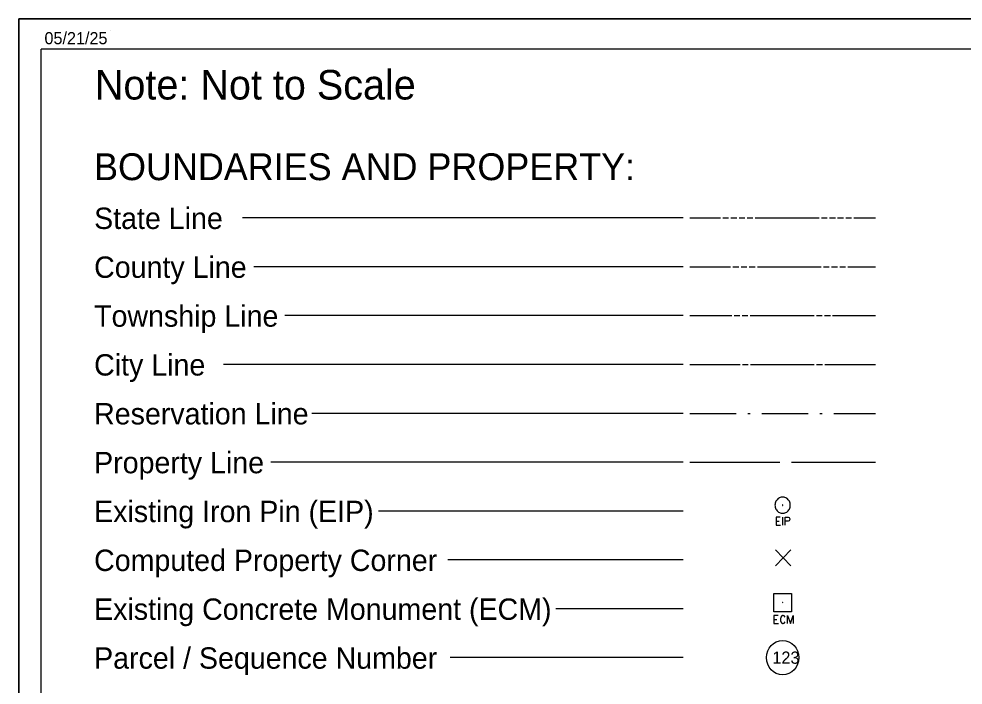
# Model space of a CAD drawing. Extents: x 2025847 to 2026166, y 840763 to 840870.
# Drawn here: x 2026023.88 to 2026057.38, y 840846.45 to 840870.09 of the extents above; entities that cross this region are included whole.
import ezdxf

# ---------------------------------------------------------------- set-up
doc = ezdxf.new("R2010")
doc.units = 0
for name, color, linetype in [('Sheet_Plan', 7, 'Continuous'), ('Sheet_Plot_Border_Outside_CELL', 7, 'Continuous'), ('Sheet_Symbology', 7, 'Continuous'), ('z - Construction', 7, 'Continuous')]:
    doc.layers.add(name, color=color, linetype=linetype)

msp = doc.modelspace()

# ---------------------------------------------------------------- linework, layer by layer
at = {"layer": 'Sheet_Plan'}
for p, q in [((2026027.113, 840869.656), (2026027.113, 840869.656)), ((2026024.668, 840780.981), (2026024.668, 840869.009)), ((2026164.548, 840869.009), (2026024.668, 840869.009))]:
    msp.add_line(p, q, dxfattribs=at)
at = {"layer": 'Sheet_Plot_Border_Outside_CELL'}
msp.add_lwpolyline([(2026023.879, 840870.085), (2026165.546, 840870.085), (2026165.546, 840778.419), (2026023.879, 840778.419)], close=True, dxfattribs=at)
at = {"layer": 'Sheet_Symbology'}
for p, q in [((2026047.446, 840863.026), (2026031.807, 840863.026)), ((2026047.682, 840863.026), (2026048.769, 840863.026)), ((2026048.851, 840863.026), (2026049.057, 840863.026)), ((2026049.139, 840863.026), (2026049.345, 840863.026)), ((2026049.428, 840863.026), (2026049.633, 840863.026)), ((2026049.716, 840863.026), (2026049.921, 840863.026)), ((2026050.004, 840863.026), (2026052.267, 840863.026)), ((2026052.35, 840863.026), (2026052.556, 840863.026)), ((2026052.638, 840863.026), (2026052.844, 840863.026)), ((2026052.926, 840863.026), (2026053.132, 840863.026)), ((2026053.214, 840863.026), (2026053.42, 840863.026)), ((2026053.502, 840863.026), (2026054.268, 840863.026)), ((2026047.446, 840861.293), (2026032.217, 840861.293)), ((2026047.682, 840861.293), (2026049.13, 840861.293)), ((2026049.212, 840861.293), (2026049.418, 840861.293)), ((2026049.501, 840861.293), (2026049.706, 840861.293)), ((2026049.789, 840861.293), (2026049.994, 840861.293)), ((2026050.077, 840861.293), (2026052.34, 840861.293)), ((2026052.423, 840861.293), (2026052.629, 840861.293)), ((2026052.711, 840861.293), (2026052.917, 840861.293)), ((2026052.999, 840861.293), (2026053.205, 840861.293)), ((2026053.287, 840861.293), (2026054.268, 840861.293)), ((2026047.446, 840859.56), (2026033.312, 840859.56)), ((2026047.682, 840859.56), (2026049.168, 840859.56)), ((2026049.251, 840859.56), (2026049.456, 840859.56)), ((2026049.539, 840859.56), (2026049.744, 840859.56)), ((2026049.827, 840859.56), (2026052.09, 840859.56)), ((2026052.173, 840859.56), (2026052.379, 840859.56)), ((2026052.461, 840859.56), (2026052.667, 840859.56)), ((2026052.749, 840859.56), (2026054.268, 840859.56)), ((2026047.446, 840857.827), (2026031.141, 840857.827)), ((2026047.682, 840857.827), (2026049.464, 840857.827)), ((2026049.546, 840857.827), (2026049.752, 840857.827)), ((2026049.834, 840857.827), (2026052.098, 840857.827)), ((2026052.18, 840857.827), (2026052.386, 840857.827)), ((2026052.468, 840857.827), (2026054.268, 840857.827)), ((2026047.446, 840856.094), (2026034.269, 840856.094)), ((2026047.682, 840856.094), (2026049.329, 840856.094)), ((2026049.74, 840856.094), (2026049.823, 840856.094)), ((2026050.234, 840856.094), (2026051.881, 840856.094)), ((2026052.292, 840856.094), (2026052.374, 840856.094)), ((2026052.786, 840856.094), (2026054.268, 840856.094)), ((2026047.446, 840854.361), (2026032.821, 840854.361)), ((2026047.682, 840854.361), (2026050.872, 840854.361)), ((2026051.284, 840854.361), (2026054.268, 840854.361)), ((2026047.446, 840852.628), (2026036.639, 840852.628)), ((2026050.976, 840852.13), (2026050.976, 840852.407)), ((2026050.739, 840852.269), (2026050.847, 840852.269)), ((2026051.264, 840850.685), (2026050.72, 840851.258)), ((2026050.72, 840850.685), (2026051.264, 840851.258)), ((2026047.446, 840850.895), (2026039.095, 840850.895)), ((2026047.446, 840849.162), (2026042.933, 840849.162)), ((2026050.664, 840848.781), (2026050.772, 840848.781)), ((2026047.446, 840847.429), (2026039.174, 840847.429))]:
    msp.add_line(p, q, dxfattribs=at)
for points in [[(2026051.246, 840852.836), (2026051.244, 840852.873), (2026051.238, 840852.907), (2026051.227, 840852.942), (2026051.213, 840852.974), (2026051.194, 840853.004), (2026051.172, 840853.032), (2026051.148, 840853.057), (2026051.119, 840853.078), (2026051.091, 840853.096), (2026051.058, 840853.108), (2026051.025, 840853.117), (2026050.993, 840853.121), (2026050.958, 840853.121), (2026050.923, 840853.117), (2026050.89, 840853.108), (2026050.859, 840853.096), (2026050.828, 840853.078), (2026050.8, 840853.057), (2026050.776, 840853.032), (2026050.754, 840853.004), (2026050.737, 840852.974), (2026050.721, 840852.942), (2026050.71, 840852.907), (2026050.704, 840852.873), (2026050.702, 840852.836), (2026050.704, 840852.799), (2026050.71, 840852.765), (2026050.721, 840852.73), (2026050.737, 840852.698), (2026050.754, 840852.668), (2026050.776, 840852.64), (2026050.8, 840852.615), (2026050.828, 840852.594), (2026050.859, 840852.576), (2026050.89, 840852.564), (2026050.923, 840852.555), (2026050.958, 840852.55), (2026050.993, 840852.55), (2026051.025, 840852.555), (2026051.058, 840852.564), (2026051.091, 840852.576), (2026051.119, 840852.594), (2026051.148, 840852.615), (2026051.172, 840852.64), (2026051.194, 840852.668), (2026051.213, 840852.698), (2026051.227, 840852.73), (2026051.238, 840852.765), (2026051.244, 840852.799), (2026051.246, 840852.836)], [(2026050.979, 840852.843), (2026050.973, 840852.845), (2026050.968, 840852.841), (2026050.966, 840852.834), (2026050.971, 840852.829), (2026050.977, 840852.827), (2026050.982, 840852.831), (2026050.984, 840852.838), (2026050.979, 840852.843)], [(2026050.891, 840852.407), (2026050.739, 840852.407), (2026050.739, 840852.13), (2026050.901, 840852.13)], [(2026051.063, 840852.13), (2026051.063, 840852.407), (2026051.169, 840852.407), (2026051.2, 840852.396), (2026051.227, 840852.352), (2026051.227, 840852.326), (2026051.202, 840852.283), (2026051.169, 840852.272), (2026051.063, 840852.272)], [(2026050.666, 840849.707), (2026051.283, 840849.707), (2026051.283, 840849.058), (2026050.666, 840849.058), (2026050.666, 840849.707)], [(2026050.973, 840849.39), (2026050.97, 840849.387), (2026050.97, 840849.381), (2026050.976, 840849.374), (2026050.982, 840849.378), (2026050.985, 840849.384), (2026050.979, 840849.39), (2026050.973, 840849.39)], [(2026050.816, 840848.918), (2026050.664, 840848.918), (2026050.664, 840848.641), (2026050.826, 840848.641)], [(2026051.065, 840848.864), (2026051.031, 840848.91), (2026050.998, 840848.918), (2026050.975, 840848.918), (2026050.944, 840848.91), (2026050.909, 840848.864), (2026050.901, 840848.803), (2026050.901, 840848.77), (2026050.901, 840848.748), (2026050.903, 840848.728), (2026050.909, 840848.693), (2026050.944, 840848.65), (2026050.975, 840848.641), (2026050.994, 840848.641), (2026051.029, 840848.65), (2026051.065, 840848.693)], [(2026051.15, 840848.641), (2026051.15, 840848.918), (2026051.249, 840848.641), (2026051.345, 840848.918), (2026051.345, 840848.641)]]:
    msp.add_lwpolyline(points, dxfattribs=at)
msp.add_ellipse((2026050.975, 840847.429), major_axis=(0, 0.607), ratio=0.95, dxfattribs=at)
at = {"layer": 'z - Construction'}
for p, q in [((2026165.546, 840870.085), (2026023.879, 840870.085)), ((2026023.879, 840870.085), (2026023.879, 840778.419))]:
    msp.add_line(p, q, dxfattribs=at)

# ---------------------------------------------------------------- texts
at = {"layer": 'Sheet_Plan'}
msp.add_text('05/21/25', height=0.4294, rotation=0, dxfattribs=at).set_placement((2026024.787, 840869.187))
at = {"layer": 'Sheet_Symbology'}
for s, height, p in [('Note: Not to Scale', 1.04911, (2026026.575, 840867.225)), ('BOUNDARIES AND PROPERTY:', 0.95314, (2026026.547, 840864.365)), ('State Line', 0.7582, (2026026.548, 840862.633)), ('County Line', 0.75818, (2026026.548, 840860.9)), ('Township Line', 0.75818, (2026026.548, 840859.167)), ('City Line', 0.7582, (2026026.548, 840857.434)), ('Reservation Line', 0.75818, (2026026.548, 840855.701)), ('Property Line', 0.75818, (2026026.548, 840853.968)), ('Existing Iron Pin (EIP)', 0.75818, (2026026.548, 840852.235)), ('Computed Property Corner', 0.75818, (2026026.548, 840850.502)), ('Existing Concrete Monument (ECM)', 0.75818, (2026026.548, 840848.769)), ('Parcel / Sequence Number', 0.75818, (2026026.548, 840847.036)), ('123', 0.4332, (2026050.607, 840847.212))]:
    msp.add_text(s, height=height, dxfattribs=at).set_placement(p)

doc.saveas('drawing.dxf')
